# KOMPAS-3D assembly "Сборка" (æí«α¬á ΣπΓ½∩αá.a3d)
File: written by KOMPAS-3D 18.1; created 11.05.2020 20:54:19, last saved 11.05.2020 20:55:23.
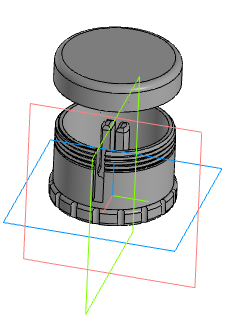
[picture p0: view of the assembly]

Document properties: Автор: Leha; Полное имя файла: C:\Users\Leha\Desktop\Сборка футляра.a3d

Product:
- Part/product: Сборка
    Масса: 0.0588262
  - Component [detail]: Деталь  | Материал: Фторопласт-4  ГОСТ 10007-80 Е (density 2200 kg/m3); Масса: 0.0058645; source file: Крышка.m3d
  - Component [detail]: Деталь  | Масса: 0.0429811; source file: Крутилка.m3d
  - Component [detail]: Деталь  | Материал: Фторопласт-4  ГОСТ 10007-80 Е (density 2200 kg/m3); Масса: 0.00998055; source file: Футляр.m3d

Referenced files in C:\Users\Leha\Desktop\: Футляр.m3d, Крутилка.m3d, Крышка.m3d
